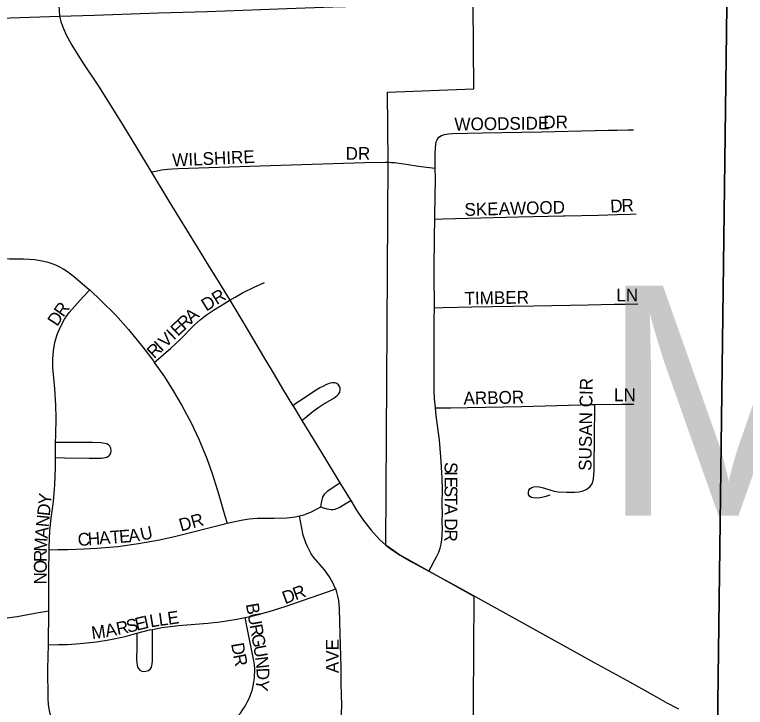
# Model space of a CAD drawing. Extents: x -97 to 34, y -21 to 22.
# Drawn here: x 7.079 to 7.621, y 18.604 to 19.118 of the extents above; entities that cross this region are included whole.
import ezdxf

# ---------------------------------------------------------------- set-up
doc = ezdxf.new("R2010")
doc.units = 0
for name, color, linetype in [('GM_X_City_Street', 7, 'Continuous'), ('GM_X_City_Street_Text', 7, 'Continuous'), ('GM_X_Corporation', 7, 'Continuous'), ('GM_X_Section', 7, 'Continuous'), ('GM_X_State_Route', 7, 'Continuous'), ('GM_X_Township_Subdivision', 7, 'Continuous'), ('GM_X_Township_Subdivision_Text', 7, 'Continuous'), ('GM_X_Township_Text', 7, 'Continuous')]:
    doc.layers.add(name, color=color, linetype=linetype)

msp = doc.modelspace()

# ---------------------------------------------------------------- linework, layer by layer
at = {"layer": 'GM_X_City_Street'}
for points in [[(7.11161, 19.15738), (7.11151, 19.13788), (7.11158, 19.12515), (7.11208, 19.11727)], [(7.18008, 19.00172), (7.18347, 19.00239), (7.18761, 19.0032), (7.19224, 19.00369), (7.19588, 19.00407), (7.20008, 19.00431), (7.26097, 19.00636), (7.29189, 19.00727), (7.33823, 19.00873), (7.35362, 19.00898), (7.35579, 19.00899)], [(7.03602, 18.93755), (7.07505, 18.93729), (7.08527, 18.93713), (7.09369, 18.93663), (7.10039, 18.93556), (7.10339, 18.93484), (7.10633, 18.93389), (7.10918, 18.93272), (7.11197, 18.93137), (7.11466, 18.92986), (7.11728, 18.92821), (7.12226, 18.92457), (7.13403, 18.91457), (7.13444, 18.91418)], [(7.23844, 18.90647), (7.24249, 18.90885), (7.24772, 18.91194), (7.25651, 18.91629), (7.26418, 18.91967)], [(7.10917, 18.80084), (7.1093, 18.80649), (7.10959, 18.81936), (7.10931, 18.82868), (7.10846, 18.8411), (7.10716, 18.85661), (7.10705, 18.86283), (7.1075, 18.86904), (7.10859, 18.87516), (7.11037, 18.88111), (7.11276, 18.88686), (7.11569, 18.89235), (7.11927, 18.89743), (7.12543, 18.90445), (7.12966, 18.90901), (7.13444, 18.91418)], [(7.13444, 18.91418), (7.14306, 18.90614), (7.15358, 18.89574), (7.16315, 18.88485), (7.17397, 18.87161), (7.18143, 18.86173), (7.18238, 18.86039)], [(7.18238, 18.86039), (7.18544, 18.863), (7.19467, 18.87086), (7.20126, 18.87714), (7.21188, 18.88797), (7.21635, 18.89208), (7.22111, 18.8958), (7.22621, 18.89908), (7.23844, 18.90647)], [(7.18238, 18.86039), (7.19004, 18.84956), (7.19648, 18.83933), (7.20292, 18.82844), (7.21001, 18.81492), (7.21546, 18.80338), (7.2214, 18.78902), (7.22536, 18.77797), (7.23027, 18.76223), (7.23478, 18.74646), (7.23632, 18.74106)], [(7.29187, 18.81732), (7.29419, 18.81921), (7.30025, 18.82414), (7.3026, 18.82585), (7.30457, 18.82728), (7.30743, 18.82915), (7.31558, 18.8339), (7.31811, 18.83576), (7.31909, 18.83689), (7.31996, 18.83826), (7.32034, 18.83971), (7.32028, 18.84114), (7.31987, 18.84244), (7.31898, 18.84381), (7.31783, 18.8447), (7.31626, 18.84522), (7.31452, 18.84526), (7.3129, 18.8449), (7.31018, 18.84399), (7.30743, 18.84253), (7.30527, 18.84141), (7.30251, 18.83981), (7.29464, 18.8347), (7.29207, 18.8329), (7.28747, 18.8298), (7.28521, 18.82827)], [(7.10904, 18.78972), (7.11569, 18.78959), (7.13399, 18.78923), (7.14313, 18.78938), (7.14612, 18.78974), (7.14763, 18.79025), (7.14852, 18.79095), (7.14937, 18.79184), (7.15008, 18.7931), (7.15045, 18.79473), (7.15008, 18.79669), (7.14945, 18.79828), (7.14845, 18.79924), (7.14723, 18.79987), (7.14559, 18.80027), (7.14261, 18.8007), (7.13657, 18.80101), (7.11537, 18.80088), (7.10917, 18.80084)], [(7.10904, 18.78972), (7.10917, 18.80084)], [(7.10432, 18.72134), (7.10434, 18.72321), (7.10488, 18.73563), (7.10582, 18.74491), (7.10749, 18.75724), (7.10869, 18.7696), (7.10895, 18.78203), (7.10904, 18.78972)], [(7.30597, 18.75322), (7.30644, 18.75619), (7.30683, 18.75828), (7.30749, 18.76026), (7.3082, 18.76165), (7.30898, 18.76284), (7.31107, 18.76497), (7.31734, 18.76922), (7.32008, 18.77108)], [(7.30597, 18.75322), (7.30784, 18.75235), (7.31032, 18.75164), (7.3135, 18.75118), (7.31509, 18.75114), (7.31664, 18.75143), (7.31965, 18.75264), (7.3252, 18.7561), (7.32807, 18.75788)], [(7.29002, 18.74641), (7.29321, 18.7472), (7.29912, 18.74948), (7.30597, 18.75322)], [(7.23632, 18.74106), (7.24671, 18.74343), (7.25279, 18.74436), (7.25892, 18.74482), (7.27133, 18.74482), (7.28076, 18.74499), (7.28703, 18.74567), (7.29002, 18.74641)], [(7.31694, 18.69226), (7.31668, 18.69295), (7.31539, 18.69583), (7.31232, 18.70135), (7.30864, 18.70647), (7.30061, 18.71589), (7.29888, 18.71838), (7.29596, 18.72368), (7.29477, 18.72646), (7.29294, 18.73228), (7.29162, 18.73866), (7.29002, 18.74641)], [(7.10432, 18.72134), (7.11068, 18.72149), (7.11824, 18.72165), (7.1303, 18.72202), (7.13967, 18.72245), (7.15525, 18.72386), (7.17074, 18.72601), (7.18613, 18.72875), (7.19834, 18.73143), (7.23461, 18.74067), (7.23632, 18.74106)], [(7.10402, 18.6761), (7.10418, 18.70455), (7.10432, 18.72134)], [(7.24973, 18.67116), (7.25565, 18.67242), (7.26765, 18.67545), (7.27946, 18.67914), (7.31168, 18.69042), (7.31694, 18.69226)], [(7.31569, 18.50214), (7.315, 18.53838), (7.31531, 18.55073), (7.31629, 18.56304), (7.31866, 18.58145), (7.32079, 18.59536), (7.32105, 18.59783), (7.32128, 18.59991), (7.32148, 18.60615), (7.32103, 18.62175), (7.3209, 18.63414), (7.32028, 18.65893), (7.31978, 18.67752), (7.31924, 18.6838), (7.31865, 18.68691), (7.31778, 18.68997), (7.31694, 18.69226)], [(7.07116, 18.67061), (7.08057, 18.67193), (7.09652, 18.67476), (7.10402, 18.6761)], [(7.10387, 18.6507), (7.10389, 18.65164), (7.10402, 18.6761)], [(7.18092, 18.66228), (7.18802, 18.66369), (7.20043, 18.66511), (7.22211, 18.66677), (7.23132, 18.66782), (7.24353, 18.66984), (7.24973, 18.67116)], [(7.23641, 18.58984), (7.24214, 18.59532), (7.24628, 18.60011), (7.24814, 18.60269), (7.24983, 18.60538), (7.25136, 18.60817), (7.2527, 18.61105), (7.25486, 18.61701), (7.25566, 18.6201), (7.25626, 18.62322), (7.25664, 18.62637), (7.25688, 18.63271), (7.25664, 18.63593), (7.25611, 18.63904), (7.25126, 18.66346), (7.24973, 18.67116)], [(7.10387, 18.6507), (7.11135, 18.65094), (7.11806, 18.65116), (7.1273, 18.65176), (7.13958, 18.65304), (7.14872, 18.65448), (7.1608, 18.65709), (7.16949, 18.65939)], [(7.16949, 18.65939), (7.16945, 18.6555), (7.16938, 18.64889), (7.16926, 18.64021), (7.16936, 18.63722), (7.17002, 18.63426), (7.17138, 18.63225), (7.17313, 18.63127), (7.17371, 18.6311), (7.17604, 18.63117), (7.17817, 18.63183), (7.17949, 18.63298), (7.18027, 18.63434), (7.18072, 18.63658), (7.18092, 18.6389), (7.18092, 18.64169), (7.18092, 18.65271), (7.18092, 18.65727), (7.18092, 18.66228)], [(7.16949, 18.65939), (7.17882, 18.66186), (7.18092, 18.66228)], [(7.11849, 18.57639), (7.11657, 18.57805), (7.11389, 18.58133), (7.10968, 18.58739), (7.10826, 18.59015), (7.10616, 18.596), (7.10458, 18.60203), (7.10395, 18.60624), (7.10357, 18.61127), (7.10349, 18.63301), (7.10387, 18.6507)]]:
    msp.add_lwpolyline(points, dxfattribs=at)
at = {"layer": 'GM_X_Corporation'}
msp.add_lwpolyline([(7.41884, 18.51601), (7.41931, 18.60748), (7.41971, 18.68656), (7.38595, 18.70546), (7.36344, 18.71801), (7.35418, 18.72483), (7.35578, 19.00899), (7.35539, 19.06097), (7.41956, 19.06333), (7.41891, 19.12628)], dxfattribs=at)
at = {"layer": 'GM_X_Section'}
for points in [[(8.62978, 19.48154), (8.62974, 19.47434), (8.61662, 18.45604), (7.59861, 18.45475), (7.61097, 19.41205)], [(6.60805, 19.46219), (7.61097, 19.41205), (7.59861, 18.45475), (6.59547, 18.46625)]]:
    msp.add_lwpolyline(points, close=True, dxfattribs=at)
at = {"layer": 'GM_X_State_Route'}
for points in [[(6.89236, 19.10958), (6.89936, 19.10983), (6.97809, 19.11263), (7.03869, 19.11478), (7.11208, 19.11727), (7.13801, 19.1181), (7.18551, 19.11967), (7.22178, 19.12086), (7.2612, 19.12232), (7.28074, 19.12305), (7.31482, 19.12415), (7.3524, 19.12513), (7.35669, 19.1252)], [(7.11208, 19.11727), (7.113, 19.11333), (7.11424, 19.10987), (7.11677, 19.10386), (7.12128, 19.0958), (7.12944, 19.08267), (7.14151, 19.06464), (7.15944, 19.03561), (7.16913, 19.01974), (7.18008, 19.00172), (7.19325, 18.98004), (7.21419, 18.94579), (7.22232, 18.93263), (7.23051, 18.91947), (7.23844, 18.90647), (7.24668, 18.89292), (7.25593, 18.87706), (7.2634, 18.86449), (7.27121, 18.85145), (7.27758, 18.84085), (7.28521, 18.82827), (7.28562, 18.82758), (7.29187, 18.81732), (7.30175, 18.8011), (7.32008, 18.77108), (7.32277, 18.76667), (7.32807, 18.75788), (7.33236, 18.75077), (7.33756, 18.74314), (7.3433, 18.73591), (7.34947, 18.72903), (7.35418, 18.72483)], [(7.35418, 18.72483), (7.35838, 18.72143), (7.36344, 18.71801), (7.37408, 18.71186), (7.38595, 18.70547), (7.40398, 18.69575), (7.4204, 18.6867)], [(7.4204, 18.6867), (7.45715, 18.66634), (7.50876, 18.63776), (7.53321, 18.62421), (7.55221, 18.61377), (7.5627, 18.60782), (7.57133, 18.60334)]]:
    msp.add_lwpolyline(points, dxfattribs=at)
at = {"layer": 'GM_X_Township_Subdivision'}
for points in [[(7.39358, 19.02753), (7.39558, 19.0288), (7.39764, 19.0295), (7.40071, 19.02993), (7.40383, 19.03018), (7.42575, 19.03074), (7.46964, 19.03149), (7.50946, 19.03241), (7.51905, 19.03262), (7.5257, 19.03276), (7.5339, 19.03293), (7.53793, 19.03302)], [(7.39087, 19.00441), (7.39074, 19.0157), (7.39122, 19.0224), (7.39153, 19.02404), (7.39216, 19.02553), (7.39358, 19.02753)], [(7.35579, 19.00899), (7.35833, 19.00884), (7.36071, 19.00871), (7.36239, 19.0085), (7.36559, 19.00802), (7.36917, 19.00748), (7.37839, 19.00604), (7.38436, 19.00526), (7.39087, 19.00441)], [(7.39057, 18.96665), (7.3906, 18.96924), (7.39095, 18.99711), (7.39087, 19.00441)], [(7.39016, 18.90086), (7.39017, 18.91047), (7.39012, 18.91633), (7.39006, 18.92418), (7.39002, 18.92896), (7.39037, 18.95373), (7.39057, 18.96665)], [(7.39057, 18.96665), (7.39654, 18.96685), (7.41524, 18.96751), (7.45252, 18.96835), (7.48547, 18.96909), (7.48704, 18.96913), (7.51186, 18.96969), (7.52587, 18.97013), (7.53561, 18.97044), (7.53995, 18.97065)], [(7.39016, 18.90086), (7.39644, 18.90101), (7.41801, 18.90152), (7.46395, 18.90239), (7.50432, 18.90315), (7.52356, 18.90353), (7.53139, 18.90368), (7.54104, 18.90387)], [(7.39099, 18.82667), (7.39039, 18.83326), (7.39011, 18.83938), (7.39002, 18.84555), (7.39001, 18.86102), (7.39011, 18.88432), (7.39014, 18.89202), (7.39016, 18.90086)], [(7.38595, 18.70547), (7.38768, 18.70865), (7.39019, 18.71329), (7.39201, 18.71665), (7.39337, 18.71953), (7.39447, 18.72251), (7.39521, 18.72557), (7.39571, 18.72867), (7.39587, 18.73183), (7.39615, 18.73789), (7.39603, 18.74098), (7.3961, 18.75004), (7.39592, 18.75311), (7.39592, 18.75615), (7.39608, 18.76547), (7.39585, 18.77472), (7.39505, 18.79022), (7.39392, 18.80258), (7.39152, 18.821), (7.39099, 18.82667)], [(7.39099, 18.82667), (7.39638, 18.82667), (7.4025, 18.82668), (7.41482, 18.82699), (7.45488, 18.82769), (7.50736, 18.82917), (7.50917, 18.82919)], [(7.47585, 18.76198), (7.47294, 18.76092), (7.46996, 18.76007), (7.46688, 18.75961), (7.46378, 18.75976), (7.46222, 18.76022), (7.46097, 18.76088), (7.46005, 18.76238), (7.45993, 18.76402), (7.46021, 18.76546), (7.46115, 18.76672), (7.46254, 18.76754), (7.4639, 18.76806), (7.46698, 18.76818), (7.47003, 18.76758), (7.47595, 18.7657), (7.47894, 18.76488), (7.48199, 18.76433), (7.48819, 18.76401), (7.4944, 18.76416), (7.49749, 18.76442), (7.50052, 18.76509), (7.50336, 18.76634), (7.50578, 18.76827), (7.50738, 18.77088), (7.50812, 18.77389), (7.50867, 18.78009), (7.50881, 18.78629), (7.50892, 18.8012), (7.50898, 18.80902), (7.50911, 18.82344), (7.50917, 18.82919)], [(7.50917, 18.82919), (7.52898, 18.82937), (7.53818, 18.82939)]]:
    msp.add_lwpolyline(points, dxfattribs=at)

# ---------------------------------------------------------------- texts
at = {"layer": 'GM_X_City_Street_Text'}
for s, rotation, p in [('WILSHIRE', 2.5623, (7.19591, 19.00573)), ('DR', 0, (7.32432, 19.01072)), ('DR', 32.014, (7.22095, 18.89799)), ('R', 54.4708, (7.11482, 18.89345)), ('D', 56.8433, (7.11032, 18.88656)), ('A', 41.5355, (7.21007, 18.88901)), ('E', 43.3765, (7.19983, 18.87933)), ('R', 43.392, (7.20468, 18.88391)), ('I', 43.3617, (7.1968, 18.87647)), ('V', 43.3617, (7.19074, 18.87074)), ('R', 43.3683, (7.18226, 18.86273)), ('I', 43.3617, (7.18771, 18.86788)), ('Y', 84.396, (7.1056, 18.7544)), ('D', 84.396, (7.10479, 18.7461)), ('N', 84.396, (7.10397, 18.73781)), ('DR', 15.526, (7.20218, 18.73483)), ('U', 12.5924, (7.17302, 18.72802)), ('A', 84.4612, (7.10317, 18.72952)), ('C', 4.3019, (7.12586, 18.72406)), ('H', 4.2881, (7.13334, 18.72462)), ('A', 4.2881, (7.14165, 18.72525)), ('T', 4.306, (7.14996, 18.72587)), ('E', 4.2939, (7.15661, 18.72637)), ('A', 6.4032, (7.16363, 18.72691)), ('M', 86.4827, (7.10256, 18.71963)), ('R', 89.9271, (7.10256, 18.71228)), ('O', 89.9478, (7.10255, 18.70395)), ('N', 89.9344, (7.10254, 18.69561)), ('D', 20.0597, (7.27935, 18.68088)), ('R', 20.2372, (7.2872, 18.68374)), ('B', 280.0333, (7.25025, 18.68094)), ('L', 9.332, (7.17966, 18.66367)), ('L', 7.7553, (7.18616, 18.66474)), ('E', 8.1633, (7.19284, 18.66564)), ('U', 280.0389, (7.25155, 18.67355)), ('R', 11.941, (7.15516, 18.65798)), ('S', 13.7438, (7.16281, 18.65961)), ('E', 13.8961, (7.16931, 18.66119)), ('I', 12.6047, (7.17573, 18.66278)), ('M', 7.8004, (7.13633, 18.65492)), ('A', 10.9266, (7.14679, 18.65637)), ('R', 280.0359, (7.25301, 18.66535)), ('G', 280.0389, (7.25431, 18.65796)), ('D', 279.5306, (7.23935, 18.65158)), ('AVE', 90, (7.31921, 18.62978)), ('U', 280.0389, (7.25576, 18.64976)), ('R', 281.3572, (7.24079, 18.64305)), ('N', 276.4609, (7.25719, 18.64171)), ('D', 271.749, (7.25812, 18.63363)), ('Y', 261.3568, (7.2584, 18.62576))]:
    msp.add_text(s, height=0.00947, rotation=rotation, dxfattribs=at).set_placement(p)
at = {"layer": 'GM_X_Township_Subdivision_Text'}
for s, rotation, p in [('WOODSIDE', 0.7738, (7.40513, 19.0324)), ('DR', 0, (7.47099, 19.03406)), ('SKEAWOOD', 1.4477, (7.41263, 18.96906)), ('D', 3.1047, (7.52089, 18.97155)), ('R', 2.7448, (7.52919, 18.97201)), ('TIMBER', 1.1011, (7.41262, 18.90319)), ('LN', 0, (7.52516, 18.90569)), ('SUSAN CIR', 89.2036, (7.5067, 18.77983)), ('ARBOR', 1.2003, (7.41187, 18.82906)), ('LN', 0, (7.52349, 18.83156)), ('S', 269.918, (7.39777, 18.78645)), ('I', 269.9391, (7.39776, 18.77978)), ('E', 269.918, (7.39776, 18.77561)), ('S', 269.9322, (7.39775, 18.76894)), ('T', 269.918, (7.39774, 18.76228)), ('A', 269.9253, (7.39773, 18.75561)), ('D', 269.9253, (7.39772, 18.74478)), ('R', 269.3442, (7.39771, 18.73647))]:
    msp.add_text(s, height=0.00947, rotation=rotation, dxfattribs=at).set_placement(p)
at = {"layer": 'GM_X_Township_Text'}
msp.add_text('MARION ', height=0.170455, rotation=0, dxfattribs=at).set_placement((7.51317, 18.74675))

doc.saveas('drawing.dxf')
